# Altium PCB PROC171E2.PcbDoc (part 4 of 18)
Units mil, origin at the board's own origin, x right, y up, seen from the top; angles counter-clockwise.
Board outline 7700 x 2300 mil, 6 copper layers (Top Layer, GND 1, SIG 1, SIG 2, GND 2, Bottom Layer), stack 61.062 mil thick; 937 components, 687 nets, 11931 pads, 1719 vias.
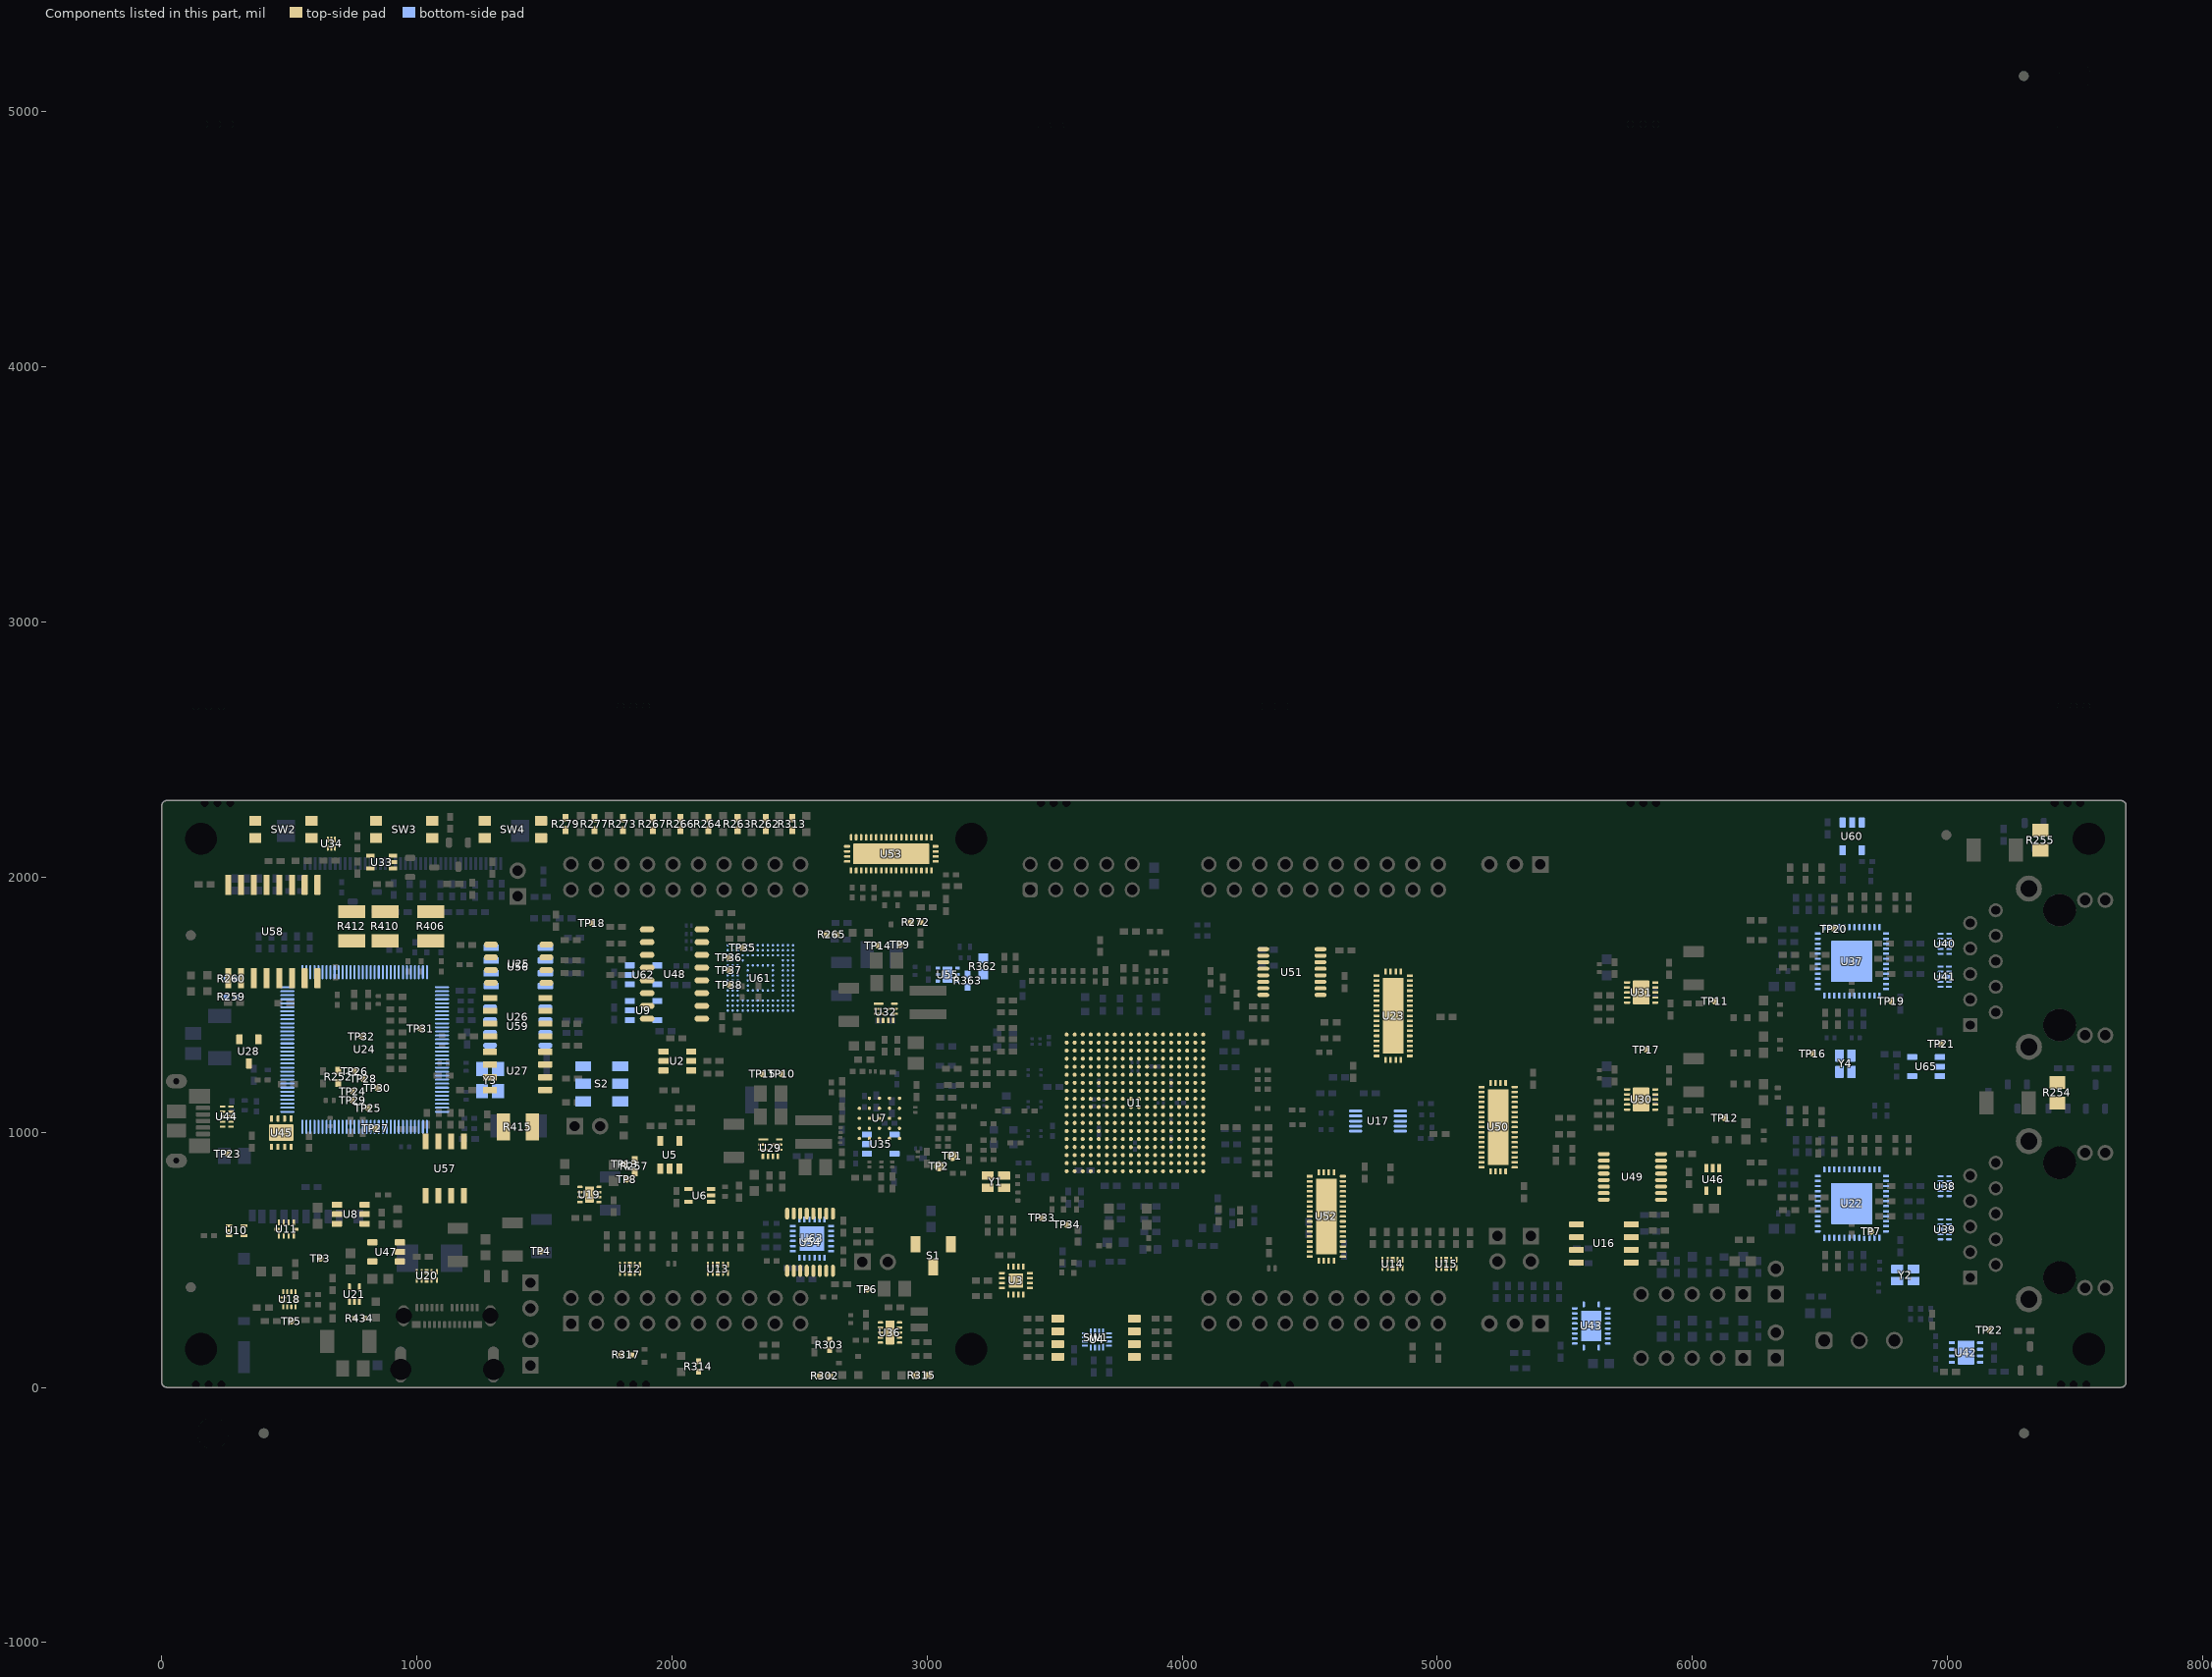
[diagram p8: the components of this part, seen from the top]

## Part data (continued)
R252: library part CMP-0078244-2, "RES, 30.0 k, 1%, 0.063 W, AEC-Q200 Grade 0, 0402", Manufacturer=Vishay-Dale, Power_W=63mW, Supplier Part Number 1=541-30.0KLCT-ND, TempCo="100 ppm/C", Tolerance_%=1%, Value2=0.063W, Value_Code=30k0, ValueDisplayed=30.0k
R254 R255: library part CMP-0021522-3, "RES, 1.00 M, 1%, 0.125 W, AEC-Q200 Grade 0, 0805", Manufacturer=Panasonic, Power_W=125mW, Supplier Part Number 1=P1.00MCCT-ND, TempCo="100 ppm/C", Tolerance_%=1%, Value2=0.125W, Value_Code=1M00, ValueDisplayed=1.00M
R257: library part CMP-0026704-1, "RES, 510, 1%, 0.1 W, 0402", Manufacturer=Panasonic, Power_W=100mW, Supplier Part Number 1=P510LCT-ND, TempCo="100 ppm/C", Tolerance_%=1%, Value2=0.1W, Value_Code=510R, ValueDisplayed=510
R259 R260 R265 R302 R314: library part CMP-0078194-1, "RES, 360, 5%, 0.1 W, AEC-Q200 Grade 0, 0402", Manufacturer=Panasonic, Power_W=100mW, Supplier Part Number 1=P360JCT-ND, TempCo="200 ppm/C", Tolerance_%=5%, Value2=0.1W, Value_Code=360R, ValueDisplayed=360
R262 R263 R264 R266 R267 R273 R277 R279: library part CMP-0026680-1, "RES, 220, 1%, 0.1 W, AEC-Q200 Grade 0, 0402", Manufacturer=Panasonic, Power_W=100mW, Supplier Part Number 1=P220LCT-ND, TempCo="100 ppm/C", Tolerance_%=1%, Value2=0.1W, Value_Code=220R, ValueDisplayed=220
R272 R303 R317: library part CMP-0078212-1, "RES, 510, 5%, 0.1 W, AEC-Q200 Grade 0, 0402", Manufacturer=Panasonic, Power_W=100mW, Supplier Part Number 1=P510JCT-ND, TempCo="200 ppm/C", Tolerance_%=5%, Value2=0.1W, Value_Code=510R, ValueDisplayed=510
R313 R315: library part CMP-0025998-3, "RES, 130, 1%, 0.063 W, AEC-Q200 Grade 0, 0402", Manufacturer=Vishay-Dale, Power_W=63mW, Supplier Part Number 1=541-130LCT-ND, TempCo="100 ppm/C", Tolerance_%=1%, Value2=0.063W, Value_Code=130R, ValueDisplayed=130
R362: library part CMP-0023078-5, "RES, 3.16 k, 1%, 0.1 W, 0603", Manufacturer=Yageo, Power_W=100mW, Supplier Part Number 1=311-3.16KHRCT-ND, TempCo="100 ppm/C", Tolerance_%=1%, Value2=0.1W, Value_Code=3k16, ValueDisplayed=3.16k
R363: library part CMP-0026088-3, "RES, 1.50 k, 1%, 0.063 W, AEC-Q200 Grade 0, 0402", Manufacturer=Vishay-Dale, Power_W=63mW, Supplier Part Number 1=541-1.50KLCT-ND, TempCo="100 ppm/C", Tolerance_%=1%, Value2=0.063W, Value_Code=1k50, ValueDisplayed=1.50k
R406 R410 R412 R415: library part CMP-0015017-3, "RES, 0, 1%, 0.75 W, AEC-Q200 Grade 0, 1210", Manufacturer=Vishay-Dale, Power_W=750mW, Supplier Part Number 1=541-0.0NCT-ND, TempCo=ppm/C, Tolerance_%=1%, Value2=0.75W, Value_Code=0
R434: library part CMP-0093717-1, "620 Ohms ±0.1% 0.063W, 1/16W Chip Resistor 0402 (1005 Metric) Automotive AEC-Q200 Thin Film", Digikey Part Number=P620CNCT-ND, Manufacturer=Panasonic, Mouser Part Number=667-ERA-2APB621X, Operating Temperature Range="-55°C to +155°C", Power_W=63mW, TempCo=15ppm/°C, Tolerance_%=0.1%
S1: library part CMP-0002139-2, "Switch, Slide, SPDT  100mA, SMT", CurrentRating_mA=100A, Manufacturer="Copal Electronics", Supplier Part Number 1=CAS120JCT-ND
S2: library part CMP-0002233-1, "Switch, Dual SPDT,  2 Pos, 0.1A, 6VDC, SMD", CurrentRating_mA=100A, Manufacturer="Copal Electronics", Supplier Part Number 1=CASD20JCT-ND
SW1: library part CMP-0093176-1, "Dip Switch SPST 4 Position Surface Mount Slide (Standard) Actuator 25mA 24VDC", Coil Resistance_ohm=100mΩ, Contact Current Rating=25mA, Digikey Part Number=732-3854-1-ND, Manufacturer=Wurth, Mouser Part Number=710-416131160804, Operating Temperature Range="-40°C to +85°C"
SW2 SW3 SW4: library part CMP-0093456-1, "Tactile Switch SPST-NO Side Actuated Surface Mount, Right Angle", Coil Resistance_ohm=100mΩ, Contact Current Rating=50mA, Digikey Part Number=732-7057-1-ND, Manufacturer="Wurth Electronics", Mouser Part Number=710-434351045816, Operating Force=160gf, Operating Temperature Range="-40°C to +85°C"
TP1 TP2: library part CMP-0003825-1, "1mm Test Point, SMT", Manufacturer=Any
TP3 TP4 TP5 TP6 TP7 TP8 TP9 TP10 TP11 TP12 TP13 TP14 TP15 TP16 TP17 TP18 TP19 TP20 TP21 TP22 TP23 TP24 TP25 TP26 TP27 TP28 TP29 TP30 TP31 TP32 TP33 TP34 TP35 TP36 TP37 TP38: library part CMP-0078143-3, "TEST POINT.  No entry in BOM.", Manufacturer=N/A
U1: library part CMP-0001698-2, "Sitara™ Microcontroller", Frequency_Fixed=200MHz, Manufacturer="Texas Instruments", Max Supply Voltage=3.465V, Min Supply Voltage=1.14V, Operating Temperature Range=to
U2: library part CMP-0051219-1, "Single 3-Input Positive-AND Gate, DBV0006A, LARGE T&R", F @ Nom Voltage(Max)(Mhz)=150, Generic Part Number=SN74LVC1G11, ICC @ Nom Voltage(Max)(mA)=0.01, Manufacturer="Texas Instruments", Operating Temperature Range(C)="-40 to 125,-40 to 85", Rating=Catalog, tpd @ Nom Voltage(Max)(ns)=20,7.8,6.2,4.6, Voltage(Nom)(V)=1.8,2.5,3.3,5
U3: library part CMP-0043157-2, "Low-Voltage 8-Bit I2C and SMBus I/O Expander, 1.65 to 5.5 V, -40 to 85 degC, 16-pin QFN (RGT), Green (RoHS & no Sb/Br)", 5V Tolerant I/O=Yes, Manufacturer="Texas Instruments", Max Frequency(kHz)=400
U4: library part CMP-0066450-2, "4-Bit Dual-Supply Bus Transceiver with Configurable Voltage-Level Shifting and 3-State Outputs, RSV0016A (UQFN-16)", Alternate Manufacturer="Texas Instruments"
U5 U9 U35 U47 U60 U62 U65: library part CMP-0051588-2, "Single 2-Input Positive-AND Gate, DBV0005A, LARGE T&R", Alternate Manufacturer="Texas Instruments", F @ Nom Voltage(Max)(Mhz)=150, Generic Part Number=SN74LVC1G08, ICC @ Nom Voltage(Max)(mA)=0.01, Operating Temperature Range(C)="-40 to 125,-40 to 85", Rating=Catalog, tpd @ Nom Voltage(Max)(ns)=4.5,6,4,5, Voltage(Nom)(V)=1.8,2.5,3.3,5
U6: library part CMP-0051704-3, "Single Schmitt-Trigger Buffer, DCK0005A, LARGE T&R", F @ Nom Voltage(Max)(Mhz)=150, Generic Part Number=SN74LVC1G17, ICC @ Nom Voltage(Max)(mA)=0.01, Manufacturer="Texas Instruments", Operating Temperature Range(C)="-40 to 125,-40 to 85", Rating=Catalog, tpd @ Nom Voltage(Max)(ns)=11,6.5,5.5,5, Voltage(Nom)(V)=1.8,2.5,3.3,5
U7: library part CMP-0120691-1, "FLASH Memory IC 256Mbit SPI - Octal I/O 133 MHz 6 ns 24-TFBGA (6x8)", Digikey Part Number=706-IS25LX256-LHLE-ND, Frequency_Fixed=133MHz, Manufacturer=ISSI, Max Supply Voltage=3.6V, Min Supply Voltage=2.7V, Mouser Part Number=870-IS25LX256-LHLE, Nominal Supply Current=0.13-48mA, Operating Temperature Range="-40°C to +105°C"
U8: library part CMP-0081995-1, "5.5V, 2A, 52mΩ Automotive High-Side Load Switch with Adjustable Rise Time & Quick Output Discharge, DBV0006A (SOT-23-6)", Alternate Manufacturer="Texas Instruments", Alternate PartNumber=TPS22918TDBVRQ1, Operating Temperature Range="-40 to 105 C", Rating=Automotive
U10: library part CMP-0043096-2, "Low-Capacitance + / - 15 kV ESD-Protection Array for High-Speed Data Interfaces, 2 Channels, -40 to +85 degC, 5-pin SOT (DRL), Green (RoHS & no Sb/Br)", Breakdown Voltage(Min)(V)=11, IO Capacitance(Typ)(pF)=1.5, IO Leakage Current(nA)=1, Manufacturer="Texas Instruments"
U11: library part CMP-0043123-1, "Low-Capacitance + / - 15 kV ESD Protection Array for High-Speed Data Interfaces, 6 Channels, -40 to +85 degC, 10-pin UQFN (RSE), Green (RoHS & no Sb/Br)", Breakdown Voltage(Min)(V)=11, IO Capacitance(Typ)(pF)=1.5, IO Leakage Current(nA)=1, Manufacturer="Texas Instruments"
U12 U13 U14 U15 U20 U44: library part CMP-0073612-3, "4-Channel ESD Protection Diode for USB Type-C and HDMI 2.0, DQA0010A (USON-10)", Alternate Manufacturer="Texas Instruments"
U16: library part CMP-0005327-2, "1024-Kb I2C CMOS Serial EEPROM, SOIC-8", Manufacturer="ON Semiconductor", Supplier Part Number 1=CAT24M01WI-GT3OSTR-ND
U17: library part CMP-0067419-2, "2-Channel, 2:1 Analog Switch with Low On-State Resistance (1ohm) and Powered Off Protection, DGS0010A (VSSOP-10)", Alternate Manufacturer="Texas Instruments", Alternate PartNumber=TS5A23159DGST, Operating Temperature Range="-40 to 85 C", Rating=Catalog
U18: library part CMP-0073635-2, "USB Type-C Configuration Channel Logic and Port Control, RWB0012A (X2QFN-12)", Alternate Manufacturer="Texas Instruments", Operating Temperature Range="-40 to 85 C", Rating=Catalog
U19: library part CMP-0073678-3, "5.5V, 4A, 16mΩ Automotive Load Switch With Adjustable Rise Time and Optional Quick Output Discharge, DSG0008B (WSON-8)", Alternate Manufacturer="Texas Instruments", Alternate PartNumber=TPS22965TDSGTQ1
U21: library part CMP-0051530-2, "Single 2-Input Positive-NOR Gate, DRL0005A, LARGE T&R", Alternate Manufacturer="Texas Instruments", F @ Nom Voltage(Max)(Mhz)=75, Generic Part Number=SN74AHC1G02, ICC @ Nom Voltage(Max)(mA)=0.01, Operating Temperature Range(C)="-40 to 125,-40 to 85", Rating=Catalog, tpd @ Nom Voltage(Max)(ns)=11.4,7.5, Voltage(Nom)(V)=3.3,5
U22 U37: library part CMP-0091377-1, "1/1 Transceiver Ethernet 48-VQFN (7x7)", Digikey Part Number=296-53377-1-ND, Manufacturer="Texas Instruments", Max Supply Voltage=3.45V, Min Supply Voltage=990mV, Mouser Part Number=595-DP83869HMRGZT, Operating Temperature Range="-40°C to +125°C"
U23 U50 U52 U53: library part CMP-0093539-2, "IC MUX/DEMUX DDR3 1:2 42WQFN", Digikey Part Number=296-28307-1-ND, Manufacturer="Texas Instruments", Max Supply Voltage=3.6V, Min Supply Voltage=3V, Mouser Part Number=595-TS3DDR3812RUAR, Nominal Supply Current=300uA, On State Resistance=8Ω, Operating Temperature Range="-40°C to +85°C"
U24: library part CMP-0029856-2, "Tiva C Series Microcontroller, 1024 KB Flash, 256 KB SRAM, 12 Bit, 20 Channels, -40 to 105 degC, 128-Pin TQFP (PDT), Green (RoHS & no Sb/Br), Tray", Manufacturer="Texas Instruments", Temperature Range="-40 to 105 degC"
U25 U59: library part CMP-0029369-1, "25 Mbps Dual Channels, 2 / 0, Digital Isolator, 3.3 V / 5 V, -40 to +125 degC, 8-pin SOIC (D), Green (RoHS & no Sb/Br)", Insulation Rating(VRMS)=2500, Manufacturer="Texas Instruments", Rating=Catalog, Supply Voltage(s)(V)="3.3, 5"
U26 U27: library part CMP-0076059-2, "High Speed, Robust EMC Dual-Channel Digital Isolator, D0008B (SOIC-8)", Alternate Manufacturer="Texas Instruments", Alternate PartNumber=ISO7721D, Operating Temperature Range="-55 to 125 C", Rating=Catalog
U28: library part CMP-0033001-1, "Precision Micropower Shunt Voltage Reference, 0.5% accuracy, 2.5 V, 15 ppm / degC, 15 mA, -40 to 125 degC, 3-pin SOT-23 (DBZ), Green (RoHS & no Sb/Br)", Manufacturer="Texas Instruments", Rating=Catalog, Temp Coeff(Max)(ppm/ degree C)=100, Temp Coeff(Typ)(ppm/ degree C)=15
U29 U32: library part CMP-0089785-1, "3V to 17V, 3A Micro Noise (20µVRMS) and Micro Ripple (200µVPP) buck converter", Manufacturer="Texas Instruments", Max Supply Voltage=17V, Min Supply Voltage=3V, Nominal Supply Current=5mA, Operating Temperature Range="-40°C to +150°C", Output Voltage=0.8-5.5V, Switching Frequency=1/2.2MHz
U30 U31: library part CMP-0036365-5, "Single Output LDO, 1.5A, Adj. (0.8 to 3.6V), Programmable Soft-Start, DRC0010J (VSON-10)", Manufacturer="Texas Instruments", Operating Temperature Range="-40 to 125 C", Power Good=TRUE, Rating=Catalog
U33: library part CMP-0051392-2, "Single Buffer/Driver With Open-Drain Output, DCK0005A, SMALL T&R", F @ Nom Voltage(Max)(Mhz)=150, Generic Part Number=SN74LVC1G07, ICC @ Nom Voltage(Max)(mA)=0.01, Manufacturer="Texas Instruments", Operating Temperature Range(C)="-40 to 125,-40 to 85", Rating=Catalog, tpd @ Nom Voltage(Max)(ns)=8.6,6,4.7,4, Voltage(Nom)(V)=1.8,2.5,3.3,5
U34: library part CMP-0051904-4, "Dual Schmitt-Trigger Buffer, DSF0006A, LARGE T&R", F @ Nom Voltage(Max)(Mhz)=150, Generic Part Number=SN74LVC2G17, ICC @ Nom Voltage(Max)(mA)=0.01, Manufacturer="Texas Instruments", Operating Temperature Range(C)="-40 to 125,-40 to 85", Rating=Catalog, tpd @ Nom Voltage(Max)(ns)=9.3,5.7,5.4,4.3, Voltage(Nom)(V)=1.8,2.5,3.3,5
U36: library part CMP-0067107-3, "28V, 0.5A Step-Down Converter with SNOOZE Mode, DQC0010A (WSON-10)", Alternate Manufacturer="Texas Instruments", Alternate PartNumber=TPS62177DQCT
U38 U39 U40 U41: library part CMP-0073613-3, "4-Channel Ultra-Low-Capacitance IEC ESD Protection Diode, DQA0010A (USON-10)", Alternate Manufacturer="Texas Instruments"
U42: library part CMP-0079884-2, "Automotive High Speed CAN Transceiver, DRB0008J (VSON-8)", Alternate Manufacturer="Texas Instruments", Alternate PartNumber=TCAN1044VDRBRQ1
U43: library part CMP-0074359-2, "8-Bit Bidirectional Voltage-Level Shifter with Auto Direction Sensing and +/-15-kV ESD Protect, RGY0020A (VQFN-20)", Alternate Manufacturer="Texas Instruments"
U45: library part CMP-0036402-3, "Single Output High PSRR LDO, 1 A, Adjustable 1.2 to 5.5 V Output, 2.7 to 5.5 V Input, 8-pin SON (DRB), -40 to 125 degC, Green (RoHS & no Sb/Br)", Manufacturer="Texas Instruments"
U46: library part CMP-0051684-3, "Single Inverter, DCK0005A, LARGE T&R", F @ Nom Voltage(Max)(Mhz)=150, Generic Part Number=SN74LVC1G04, ICC @ Nom Voltage(Max)(mA)=0.01, Manufacturer="Texas Instruments", Operating Temperature Range(C)="-40 to 125,-40 to 85", Rating=Catalog, tpd @ Nom Voltage(Max)(ns)=7.5,5.2,4.2,3.7, Voltage(Nom)(V)=1.8,2.5,3.3,5
U48: library part CMP-0044782-1, "8-Bit LED Driver with I2C Interface, D0016A, TUBE", Generic Part Number=TPIC2810, Manufacturer="Texas Instruments", Operating Temperature Range(C)="-40 to 125", Rating=Catalog
U49 U51 U54: library part CMP-0076540-1, "4-Bit One-of-2 FET Multiplexer/Demultiplexer 2.5-V/3.3-V Low-Voltage, High-Bandwidth Bus Switch, PW0016A (TSSOP-16)", Alternate Manufacturer="Texas Instruments"
U55: library part CMP-0084398-1, "500-mA LDO, DRV0006A (WSON-6)", Alternate Manufacturer="Texas Instruments", Alternate PartNumber=TLV75801PDRVT, Operating Temperature Range="-40 to 125 C", Rating=Catalog
U56 U57: library part CMP-0031336-1, "Hot-swappable, robust-EMC bidirectional I2C isolator with unidirectional clock 8-SOIC -40 to 125", Digikey Part Number=296-ISO1641BDRCT-ND, Manufacturer="Texas Instruments", Max Supply Voltage=5.5V, Min Supply Voltage=2.25V, Mouser Part Number=595-ISO1641BDR, Operating Temperature Range="-40°C to +125°C"
U58: library part CMP-0096103-1, "General purpose, 50-Mbps, six-channel (6/0) digital isolator 16-SOIC -40 to 125", Digikey Part Number=296-ISO6760DWRCT-ND, Manufacturer="Texas Instruments", Max Supply Voltage=5.5V, Min Supply Voltage=1.71V, Mouser Part Number=595-ISO6760DWR, Operating Temperature Range="-40°C to +125°C"
U61: library part CMP-0091989-1, "FLASH - NAND Memory IC 64Gb (8G x 8) MMC 153-TFBGA (11.5x13)", Digikey Part Number=MTFC8GAMALBH-AAT-ND, Manufacturer="Micron Technology", Max Supply Voltage=3.6V, Min Supply Voltage=2.7V, Mouser Part Number=340-349135-TRAY, Operating Temperature Range="-40°C to +105°C"
U63: library part CMP-0043175-2, "Low-Voltage 16-Bit I2C and SMBus I/O Expander, 16 Outputs, 1.65 to 5.5 V, -40 to 85 degC, 24-pin QFN (RTW), Green (RoHS & no Sb/Br)", 5V Tolerant I/O=Yes, Manufacturer="Texas Instruments", Max Frequency(kHz)=400
Y1: library part CMP-0084811-1, "Crystal, 25 MHz, 10 ppm, 4 pF, SMD", Frequency Stability="20 ppm", Frequency Tolerance="10 ppm", Frequency_Fixed=25MHz, Load Capacitance="4 pF", Manufacturer="Abracon Corporation", PartNumber=ABM10W-25.0000MHZ-8-K1Z-T3
Y2 Y4: library part CMP-0084811-1, "Crystal, 25 MHz, 10 ppm, 4 pF, SMD", Frequency_Fixed=25MHz, Frequency Stability="20 ppm", Frequency Tolerance="10 ppm", Load Capacitance="4 pF", Manufacturer="Abracon Corporation"
Y3: library part CMP-0004635-3, "Crystal, 16 MHz, 8pF, SMD", Frequency_Fixed=16MHz, Frequency Stability=+/-30ppm, Manufacturer=NDK, Supplier Part Number 1=644-1157-1-ND
ZZ1: library part CMP-0003616-3
ZZ2: library part CMP-0077236-1
ZZ3: library part CMP-0077237-1
ZZ4: library part CMP-0077238-1

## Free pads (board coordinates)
  round 65.36 on Mech16: 1(-281.58,414) 1(249.42,53) 1(1196.42,275) 1(1203.42,-873) 1(1504.42,253)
